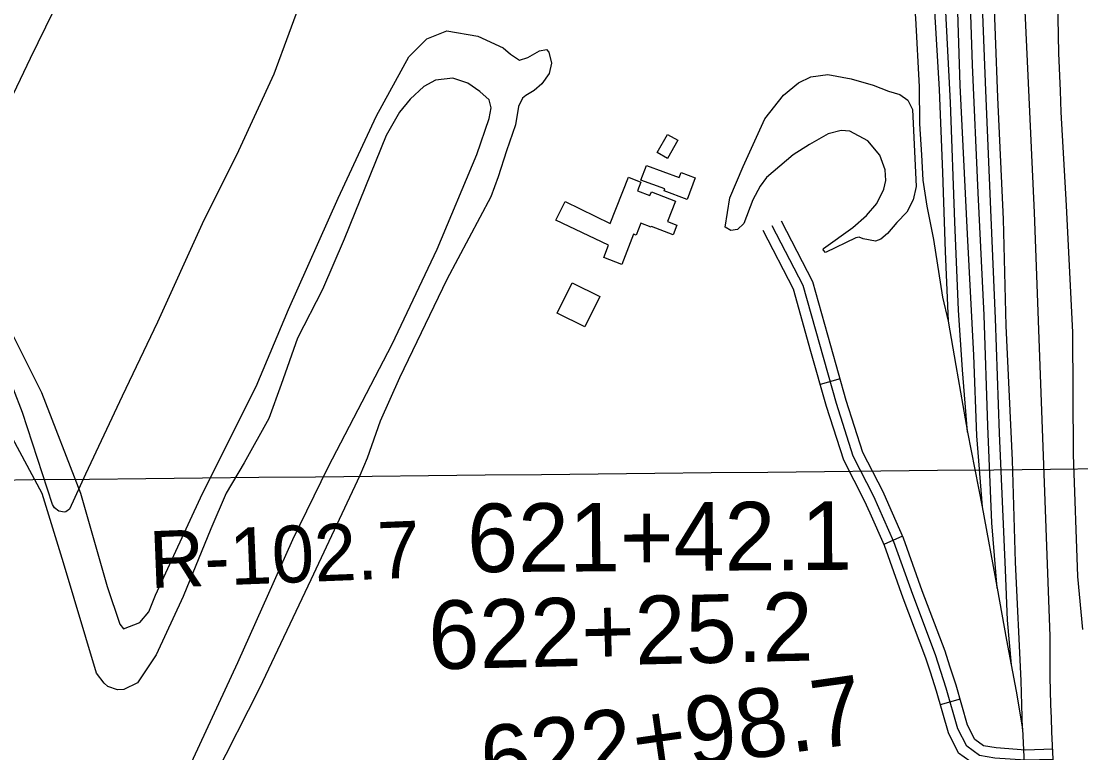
# Model space of a CAD drawing. Extents: x 3651524 to 3689615, y 505651 to 531377.
# Drawn here: x 3655705 to 3657251, y 522786 to 523853 of the extents above; entities that cross this region are included whole.
import ezdxf

# ---------------------------------------------------------------- set-up
doc = ezdxf.new("R2010")
doc.units = 0
for name, color, linetype in [('V-BLDG-OTLN', 7, 'Continuous'), ('V-GRID-MAJR', 7, 'Continuous'), ('V-LEVE-TOET', 7, 'Continuous'), ('V-RAIL-TRAK', 7, 'Continuous'), ('V-RIVR-RANG-IDEN', 7, 'Continuous'), ('V-ROAD-CNTR', 7, 'Continuous'), ('V-SITE-VEGE', 7, 'Continuous'), ('V-SURV-IDEN', 7, 'Continuous'), ('V-TOPO-SHOR', 7, 'Continuous')]:
    doc.layers.add(name, color=color, linetype=linetype)

msp = doc.modelspace()

# ---------------------------------------------------------------- linework, layer by layer
at = {"layer": 'V-BLDG-OTLN'}
for points in [[(3656647.991, 523653.191), (3656633.151, 523661.626), (3656648.259, 523688.203), (3656663.097, 523679.77)], [(3656688.697, 523624.902), (3656677.019, 523593.342), (3656643.104, 523605.892), (3656644.183, 523608.806), (3656609.412, 523621.672), (3656617.332, 523643.082), (3656665.401, 523625.301), (3656668.073, 523632.53)], [(3656564.682, 523558.219), (3656591.118, 523625.764), (3656609.353, 523618.627), (3656604.444, 523606.078), (3656622.507, 523599.009), (3656624.725, 523604.676), (3656659.824, 523590.94), (3656648.101, 523560.988), (3656661.86, 523555.601), (3656656.422, 523541.708), (3656624.848, 523554.063), (3656624.439, 523553.017), (3656609.32, 523558.936), (3656602.339, 523541.095), (3656598.716, 523542.513), (3656581.533, 523498.616), (3656555.31, 523508.878), (3656562.2, 523526.483), (3656485.269, 523563.007), (3656498.913, 523590.378)], [(3656549.324, 523451.631), (3656527.583, 523407.578), (3656487.122, 523427.544), (3656508.866, 523471.599)]]:
    msp.add_lwpolyline(points, close=True, dxfattribs=at)
at = {"layer": 'V-GRID-MAJR'}
msp.add_spline([(3655639.78, 523183.706), (3660918.553, 523238.605), (3666197.317, 523294.271), (3671476.073, 523350.705), (3676754.821, 523407.907), (3682033.561, 523465.877), (3687312.292, 523524.615)], degree=3, dxfattribs=at)
at = {"layer": 'V-LEVE-TOET'}
msp.add_lwpolyline([(3657186.256, 525146.996), (3657188.163, 524987.54), (3657185.949, 524929.125), (3657184.728, 524860.065), (3657184.01, 524820.528), (3657189.873, 524751.343), (3657196.969, 524618.366), (3657201.104, 524592.825), (3657201.383, 524575.106), (3657200.789, 524541.461), (3657200.627, 524498.951), (3657199.572, 524439.336), (3657202.507, 524304.661), (3657210.265, 524142.151), (3657215.946, 523962.553), (3657218.504, 523806.631), (3657220.953, 523751.632), (3657222.182, 523720.908), (3657229.807, 523584.378), (3657238.939, 523399.407), (3657239.92, 523221.075), (3657246.224, 523043.237), (3657253.711, 522965.757)], dxfattribs=at)
at = {"layer": 'V-RAIL-TRAK'}
for points in [[(3657166.337, 522820.885), (3657164.038, 522891.189), (3657155.878, 523064.335), (3657151.424, 523213.209), (3657142.48, 523408.805), (3657138.151, 523564.76), (3657130.065, 523742.037), (3657123.233, 523923.426), (3657117.435, 524096.529), (3657109.794, 524265.532), (3657106.489, 524412.614), (3657103.347, 524468.762), (3657097.078, 524514.928), (3657084.241, 524557.075), (3657051.322, 524632.055), (3657042.931, 524651.65)], [(3657051.662, 524450.78), (3657056.251, 524309.583), (3657061.363, 524197.895), (3657065.217, 524048.444), (3657070.241, 523898.381), (3657074.884, 523760.135), (3657085.21, 523542.666), (3657094.487, 523365.959), (3657098.905, 523248.381), (3657107.113, 523144.908)], [(3657051.662, 524450.78), (3657067.349, 524369.612), (3657084.485, 524270.114), (3657091.811, 524216.843), (3657096.132, 524160.675), (3657101.223, 524047.807), (3657106.311, 523901.287), (3657111.945, 523752.394), (3657119.885, 523566.853), (3657126.141, 523419.721), (3657132.044, 523252.52), (3657140.914, 523052.791), (3657143.75, 522979.526), (3657149.497, 522914.192)], [(3657129.228, 523026.427), (3657121.464, 523121.626), (3657115.692, 523262.846), (3657110.288, 523424.724), (3657101.633, 523603.193), (3657093.123, 523789.925), (3657087.717, 523951.803), (3657079.449, 524152.112), (3657074.718, 524251.983), (3657067.313, 524334.185), (3657067.349, 524369.612)], [(3657086.013, 523253.923), (3657078.765, 523344.981), (3657072.625, 523431.886), (3657067.226, 523560.699), (3657060.859, 523734.994), (3657053.495, 523886.278), (3657050.613, 524023.903), (3657046.941, 524150.324), (3657047.842, 524234.743), (3657050.46, 524282.525)], [(3656980.473, 524028.325), (3656987.719, 524003.988), (3657000.388, 523952.395), (3657004.019, 523923.989), (3657009.934, 523857.753), (3657015.254, 523757.874), (3657016.065, 523703.539), (3657018.816, 523658.616), (3657020.52, 523621.387), (3657026.344, 523583.495), (3657036.113, 523534.906), (3657049.388, 523450.828), (3657057.576, 523415.619)], [(3657037.823, 523868.251), (3657044.653, 523753.584), (3657049.599, 523632.455), (3657053.468, 523517.248), (3657057.576, 523415.619), (3657068.834, 523351.061), (3657086.013, 523253.923), (3657107.113, 523144.908), (3657129.228, 523026.427), (3657142.65, 522950.614), (3657149.497, 522914.192), (3657156.681, 522875.968), (3657166.337, 522820.885), (3657168.336, 522769.878)]]:
    msp.add_lwpolyline(points, dxfattribs=at)
at = {"layer": 'V-ROAD-CNTR'}
for p, q in [((3656899.942, 523331.752), (3656871.065, 523323.621)), ((3656991.271, 523102.082), (3656963.824, 523089.972)), ((3657075.041, 522864.485), (3657046.215, 522856.173))]:
    msp.add_line(p, q, dxfattribs=at)
for points in [[(3657127.963, 524714.321), (3657148.653, 524320.114), (3657183.095, 523574.183), (3657205.802, 522956)], [(3656886.391, 523379.879), (3656860.082, 523473.314), (3656814.286, 523561.89)], [(3656857.513, 523371.749), (3656832.032, 523462.246), (3656787.638, 523548.112)], [(3657210.612, 522776.446), (3657170.269, 522775.129), (3657125.793, 522778.319), (3657103.339, 522782.249), (3657084.7, 522795.677), (3657072.003, 522820.879), (3657054.847, 522880.378), (3657039.152, 522929.179), (3657005.884, 523017.073), (3656978.501, 523093.865), (3656949.267, 523160.123), (3656919.192, 523218.637), (3656894.561, 523295.521), (3656846.057, 523467.78), (3656800.962, 523555.001)], [(3656971.088, 523147.826), (3656962.811, 523166.585), (3656933.099, 523224.393), (3656908.927, 523299.843), (3656886.391, 523379.881)], [(3656943.64, 523135.716), (3656935.723, 523153.661), (3656905.285, 523212.881), (3656880.195, 523291.199), (3656857.513, 523371.749)], [(3657060.207, 522912.704), (3657053.315, 522934.133), (3657019.964, 523022.247), (3656992.446, 523099.419), (3656971.088, 523147.827)], [(3657031.647, 522903.52), (3657024.989, 522924.225), (3656991.804, 523011.899), (3656964.556, 523088.311), (3656943.64, 523135.717)], [(3657210.123, 522791.438), (3657170.562, 522790.147), (3657127.627, 522793.226), (3657109.315, 522796.431), (3657096.445, 522805.703), (3657086.028, 522826.379), (3657069.197, 522884.753), (3657060.207, 522912.706)], [(3657211.101, 522761.454), (3657169.976, 522760.111), (3657123.959, 522763.412), (3657097.363, 522768.067), (3657072.955, 522785.651), (3657057.978, 522815.379), (3657040.497, 522876.003), (3657031.647, 522903.52)]]:
    msp.add_lwpolyline(points, dxfattribs=at)
msp.add_arc((3659987.166, 522940.666), 2781.407, 179.684128, 186.247442, dxfattribs=at)
msp.add_spline([(3657129.943, 524655.414), (3657166.389, 524653.332), (3657185.57, 524640.198), (3657200.233, 524605.692), (3657221.299, 524544.671), (3657263.972, 524488.509), (3657346.94, 524446.93), (3657451.918, 524381.84), (3657518.866, 524275.788), (3657590.106, 524205.982), (3657650.646, 524044.599), (3657661.145, 523937.202), (3657682.089, 523855.232), (3657701.882, 523782.87)], degree=3, dxfattribs=at)
at = {"layer": 'V-SITE-VEGE'}
for p, q in [((3656297.25, 523827.885), (3656326.143, 523839.145)), ((3656326.143, 523839.145), (3656371.445, 523831.717)), ((3656271.038, 523801.226), (3656297.25, 523827.885)), ((3656371.445, 523831.717), (3656408.618, 523814.622)), ((3656408.618, 523814.622), (3656418.903, 523805.318)), ((3656444.546, 523800.473), (3656461.584, 523810.313)), ((3656461.584, 523810.313), (3656471.646, 523812.294)), ((3656471.646, 523812.294), (3656475.291, 523808.208)), ((3656475.291, 523808.208), (3656479.17, 523792.242)), ((3656223.407, 523715.327), (3656271.038, 523801.226)), ((3656418.903, 523805.318), (3656432.144, 523796.665)), ((3656432.144, 523796.665), (3656444.546, 523800.473)), ((3656479.17, 523792.242), (3656475.303, 523777.312)), ((3656475.303, 523777.312), (3656464.904, 523762.253)), ((3656309.725, 523767.524), (3656292.675, 523758.278)), ((3656335.216, 523770.402), (3656309.725, 523767.524)), ((3656356.751, 523763.101), (3656335.216, 523770.402)), ((3656374.218, 523750.968), (3656356.751, 523763.101)), ((3656464.904, 523762.253), (3656453.805, 523752.529)), ((3656292.675, 523758.278), (3656272.842, 523739.469)), ((3656388.124, 523738.76), (3656374.218, 523750.968)), ((3656441.472, 523745.156), (3656436.803, 523740.904)), ((3656453.805, 523752.529), (3656441.472, 523745.156)), ((3656272.842, 523739.469), (3656257.169, 523720.744)), ((3656390.733, 523726.929), (3656388.124, 523738.76)), ((3656430.978, 523728.981), (3656426.276, 523702.078)), ((3656436.803, 523740.904), (3656430.978, 523728.981)), ((3656167.534, 523595.398), (3656223.407, 523715.327)), ((3656257.169, 523720.744), (3656237.639, 523686.491)), ((3656388.067, 523711.43), (3656390.733, 523726.929)), ((3656370.085, 523658.79), (3656388.067, 523711.43)), ((3656426.276, 523702.078), (3656413.349, 523664.391)), ((3656237.639, 523686.491), (3656176.433, 523535.562)), ((3656312.186, 523520.996), (3656370.085, 523658.79)), ((3656413.349, 523664.391), (3656401.031, 523626.124)), ((3656401.031, 523626.124), (3656390.305, 523597.395)), ((3656095.262, 523432.959), (3656167.534, 523595.398)), ((3656390.305, 523597.395), (3656326.127, 523476.706)), ((3656176.433, 523535.562), (3656144.607, 523461.858)), ((3656246.577, 523382.457), (3656312.186, 523520.996)), ((3656326.127, 523476.706), (3656257.048, 523333.348)), ((3655663.251, 523454.49), (3655734.941, 523311.924)), ((3656144.607, 523461.858), (3656108.564, 523391.038)), ((3656048.158, 523320.335), (3656095.262, 523432.959)), ((3656108.564, 523391.038), (3656084.342, 523323.422)), ((3656153.251, 523202.973), (3656246.577, 523382.457)), ((3655735.766, 523164.485), (3655638.105, 523345.927)), ((3656257.048, 523333.348), (3656229.181, 523269.819)), ((3655734.941, 523311.924), (3655791.722, 523164.988)), ((3655969.82, 523164.317), (3656048.158, 523320.335)), ((3656084.342, 523323.422), (3656066.303, 523273.754)), ((3656066.303, 523273.754), (3656030.74, 523208.885)), ((3656229.181, 523269.819), (3656210.036, 523215.969)), ((3656030.74, 523208.885), (3656004.267, 523164.995)), ((3656101.793, 523097.337), (3656153.251, 523202.973)), ((3656210.036, 523215.969), (3656199.241, 523190.803)), ((3656199.241, 523190.803), (3656127.919, 523038.399)), ((3655766.925, 523063.289), (3655735.766, 523164.485)), ((3655791.722, 523164.988), (3655830.712, 523028.817)), ((3655901.218, 523015.912), (3655969.82, 523164.317)), ((3656004.267, 523164.995), (3655982.075, 523112.758)), ((3655982.075, 523112.758), (3655941.734, 523014.325)), ((3656021.489, 522918.006), (3656101.793, 523097.337)), ((3655815.333, 522902.298), (3655766.925, 523063.289)), ((3656127.919, 523038.399), (3656053.139, 522880.579)), ((3655830.712, 523028.817), (3655849.058, 522973.808)), ((3655891.568, 522991.908), (3655901.218, 523015.912)), ((3655941.734, 523014.325), (3655902.328, 522929.01)), ((3655878.184, 522976.167), (3655891.568, 522991.908)), ((3655849.058, 522973.808), (3655854.552, 522966.771)), ((3655854.552, 522966.771), (3655878.184, 522976.167)), ((3655902.328, 522929.01), (3655875.151, 522887.988)), ((3655947.337, 522758.413), (3656021.489, 522918.006)), ((3655826.337, 522887.628), (3655815.333, 522902.298)), ((3655831.789, 522882.973), (3655826.337, 522887.628)), ((3655845.58, 522877.885), (3655831.789, 522882.973)), ((3655855.091, 522878.668), (3655845.58, 522877.885)), ((3655875.151, 522887.988), (3655855.091, 522878.668)), ((3656053.139, 522880.579), (3655972.413, 522722.641))]:
    msp.add_line(p, q, dxfattribs=at)
msp.add_lwpolyline([(3656732.389, 523552.781), (3656739.278, 523595.752), (3656758.611, 523641.345), (3656789.964, 523710.973), (3656817.25, 523745.418), (3656839.497, 523763.703), (3656857.175, 523772.38), (3656882.095, 523775.841), (3656916.131, 523769.372), (3656948.445, 523759.891), (3656970.622, 523751.402), (3656987.379, 523746.377), (3656998.842, 523738.273), (3657005.651, 523724.723), (3657010.831, 523612.384), (3657006.458, 523592.666), (3656997.295, 523574.64), (3656982.72, 523559.48), (3656969.344, 523543.75), (3656959.397, 523535.226), (3656951.713, 523532.694), (3656933.803, 523535.914), (3656927.809, 523538.175), (3656923.064, 523537.487), (3656878.87, 523515.796), (3656875.22, 523519.89), (3656875.779, 523521.686), (3656918.609, 523552.271), (3656938.489, 523569.915), (3656953.614, 523587.464), (3656963.909, 523608.489), (3656966.637, 523621.035), (3656965.74, 523636.487), (3656958.183, 523657.756), (3656940.517, 523678.825), (3656914.059, 523693.18), (3656901.545, 523694.124), (3656882.61, 523688.994), (3656855.545, 523673.589), (3656831.455, 523658.243), (3656792.835, 523625.358), (3656783.564, 523612.683), (3656772.65, 523592.836), (3656759.65, 523558.075), (3656750.298, 523549.564), (3656740.806, 523548.186)], close=True, dxfattribs=at)
at = {"layer": 'V-TOPO-SHOR'}
for points in [[(3655929.321, 524239.447), (3655856.666, 524092.892), (3655785.015, 523935.682), (3655718.492, 523799.133), (3655648.573, 523654.213), (3655635.212, 523626.127)], [(3656117.383, 523895.473), (3656073.953, 523776.247), (3656022.486, 523664.362), (3655969.335, 523557.967), (3655903.895, 523414.24), (3655852.351, 523306.298), (3655798.949, 523192.403), (3655775.881, 523141.445), (3655770.429, 523137.787), (3655768.465, 523137.353), (3655760.152, 523138.768), (3655753.748, 523143.378), (3655750.887, 523148.451), (3655707.217, 523282.537), (3655641.137, 523452.882), (3655636.867, 523465.848)]]:
    msp.add_lwpolyline(points, dxfattribs=at)

# ---------------------------------------------------------------- texts
at = {"layer": 'V-RIVR-RANG-IDEN'}
msp.add_text('R-102.7', height=83, rotation=2.285117, dxfattribs=at).set_placement((3655893.743, 523026.232))
at = {"layer": 'V-SURV-IDEN'}
for s, rotation, p in [('621+42.1', 0.367875, (3656356.044, 523049.495)), ('622+25.2', 1.335213, (3656300.305, 522907.661)), ('622+98.7', 8.05204, (3656382.953, 522722.875))]:
    msp.add_text(s, height=100, rotation=rotation, dxfattribs=at).set_placement(p)

doc.saveas('drawing.dxf')
